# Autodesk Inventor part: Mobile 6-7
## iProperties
Author: Philippe
Shininess: 21.0
Angle Display Precision: 2
Document Length Units: 11269
Document Angle Units: 11283
Document Time Units: 11279
Document Mass Units: 11290
Document Length Units Precision: 3
Document Angle Units Precision: 2
Compacted: False
PropertySet Name: _Private Model Information
Created: 2002-01
Part Number: Mobile 6-7
Material: Par défaut
Document SubType Name: Modélisation
Designer: Philippe
Control State: 0
Master: False
Checked Out: False
PropertySet Name: Design Tracking Control
Density: 0.0
Volumn: 0.0
Area: 0.0
PropertySet Name: Model Information
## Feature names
1. Révolution1 [Revolution]
2. Extrusion1
3. Extrusion5
4. Extrusion6
5. Extrusion7
6. Réseau circulaire4 [Circular Pattern]
7. Extrusion10
8. Réseau circulaire6 [Circular Pattern]
